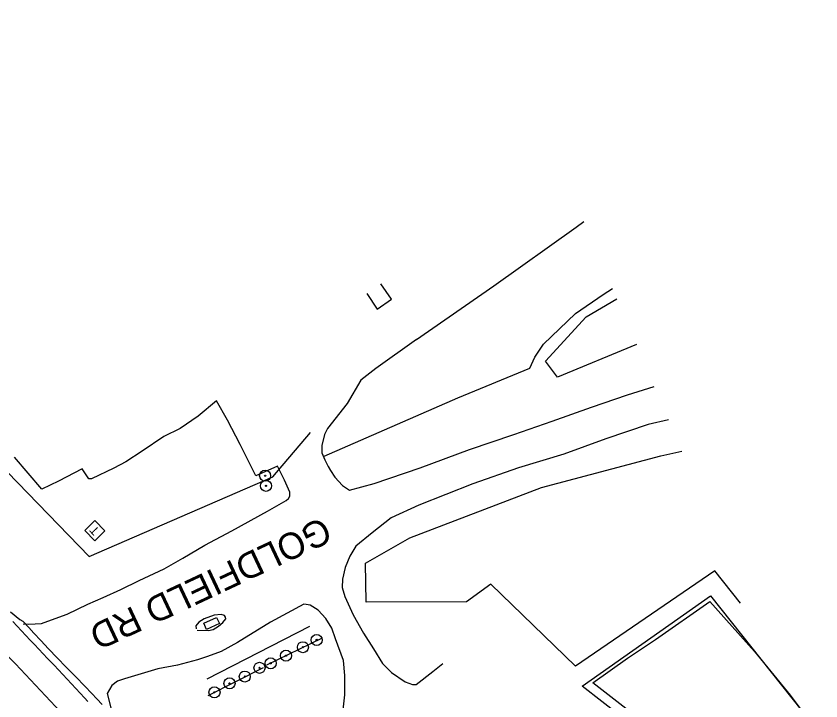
# Model space of a CAD drawing. Extents: x 474972 to 479313, y 498315 to 502691.
# Drawn here: x 477234.5 to 477551.7, y 500171.9 to 500442.1 of the extents above; entities that cross this region are included whole.
import ezdxf

# ---------------------------------------------------------------- set-up
doc = ezdxf.new("R2010")
doc.units = 0
for name, color, linetype in [('Exist Horizontal Alignment', 7, 'Continuous'), ('Exist Other Culture Area Outline', 7, 'Continuous'), ('Exist Other Culture Fence Line', 7, 'Continuous'), ('Exist Other Culture Gate', 7, 'Continuous'), ('Exist Other Culture Sign', 7, 'Continuous'), ('Exist Other Culture Sign Post CELL', 7, 'Continuous'), ('Exist Roads EOP', 7, 'Continuous'), ('Exist Roads EOT', 7, 'Continuous'), ('Exist Roads Soil', 7, 'Continuous'), ('Exist Roads Soil Text', 7, 'Continuous'), ('Exist Utilities Other Located Object CELL', 7, 'Continuous'), ('Exist Utilities Telephone Pedestal CELL', 7, 'Continuous'), ('Exist Vegetation Woods Line', 7, 'Continuous')]:
    doc.layers.add(name, color=color, linetype=linetype)

msp = doc.modelspace()

# ---------------------------------------------------------------- linework, layer by layer
at = {"layer": 'Exist Horizontal Alignment'}
msp.add_arc((475159.06, 498211.82), 2864.54, 37.33366, 48.4381, dxfattribs=at)
at = {"layer": 'Exist Other Culture Area Outline'}
msp.add_lwpolyline([(477372.66, 500332.68), (477376.85, 500326.48), (477382.44, 500330.4), (477378.3, 500336.51)], dxfattribs=at)
msp.add_lwpolyline([(477314.6, 500202.42), (477309.52, 500200.17), (477308.43, 500202.63), (477313.51, 500204.88)], close=True, dxfattribs=at)
at = {"layer": 'Exist Other Culture Fence Line'}
msp.add_line((477309.84, 500180.65), (477350.19, 500201.45), dxfattribs=at)
for points in [[(477039.4, 500442.07), (477096.14, 500405.12), (477127.29, 500368.44), (477206.77, 500287.2), (477263.29, 500228.94), (477335.66, 500260.31)], [(477355.92, 500268.54), (477408.61, 500291.48), (477437.03, 500303.18), (477439, 500307.6), (477442.35, 500312.6), (477454.97, 500324.77), (477465.82, 500332.23), (477469.57, 500334.57)], [(477493.59, 500150.54), (477480.89, 500159.66), (477457.6, 500177.83), (477508.16, 500213.44), (477544.32, 500167.89)]]:
    msp.add_lwpolyline(points, dxfattribs=at)
at = {"layer": 'Exist Other Culture Gate'}
msp.add_line((477335.66, 500260.31), (477350.53, 500277.77), dxfattribs=at)
at = {"layer": 'Exist Other Culture Sign'}
for p, q in [((477354.81, 500196.63), (477333.11, 500186.02)), ((477331.82, 500185.01), (477310.05, 500173.91))]:
    msp.add_line(p, q, dxfattribs=at)
at = {"layer": 'Exist Other Culture Sign Post CELL'}
for centre, radius in [((477352.97, 500196.01), 2.18), ((477352.97, 500196.01), 0.24), ((477347.52, 500193.13), 2.18), ((477347.52, 500193.13), 0.24), ((477340.86, 500189.8), 2.18), ((477340.86, 500189.8), 0.24), ((477330.42, 500185), 2.18), ((477334.82, 500186.8), 2.18), ((477334.82, 500186.8), 0.24), ((477324.61, 500181.56), 2.18), ((477330.42, 500185), 0.24), ((477318.6, 500178.86), 2.18), ((477324.61, 500181.56), 0.24), ((477312.67, 500175.35), 2.18), ((477318.6, 500178.86), 0.24), ((477312.67, 500175.35), 0.24)]:
    msp.add_circle(centre, radius, dxfattribs=at)
at = {"layer": 'Exist Roads EOP'}
msp.add_lwpolyline([(477232.26, 500207.11), (477235.93, 500204.1), (477237.07, 500203.39), (477237.37, 500203.15), (477239.54, 500200.85), (477241.51, 500198.72), (477244.16, 500195.84), (477247.28, 500192.5), (477250.62, 500188.97), (477254.18, 500185.27), (477257.98, 500181.39), (477261.51, 500177.78), (477264.3, 500174.92), (477266.33, 500172.8), (477268.45, 500170.49)], dxfattribs=at)
at = {"layer": 'Exist Roads EOT'}
msp.add_lwpolyline([(477262.8, 500171.72), (477261.4, 500173.22), (477259.69, 500175.05), (477257.98, 500176.87), (477256.27, 500178.7), (477254.57, 500180.52), (477252.86, 500182.35), (477251.15, 500184.17), (477249.44, 500186), (477247.73, 500187.82), (477246.9, 500188.71), (477245.18, 500190.52), (477243.46, 500192.33), (477241.74, 500194.15), (477240.02, 500195.96), (477238.3, 500197.77), (477236.58, 500199.58), (477234.85, 500201.4), (477233.13, 500203.21)], dxfattribs=at)
at = {"layer": 'Exist Roads Soil'}
for points in [[(477392.33, 500314.47), (477422.76, 500335.64), (477455.2, 500358.85), (477458.29, 500361.04)], [(477392.33, 500314.47), (477376.22, 500303.07), (477370.39, 500298.52), (477365.01, 500289.3), (477357.25, 500279.45), (477355.99, 500277), (477354.97, 500272.66), (477354.99, 500269.85), (477356.11, 500267), (477357.44, 500264.38), (477358.46, 500262.85), (477360.14, 500260.21), (477363.07, 500256.93), (477365.91, 500255.07), (477375.57, 500257.65), (477393.7, 500263.94), (477413.17, 500271.11), (477430.63, 500277.04), (477445.72, 500282.31), (477461.22, 500287.76), (477475.48, 500292.63), (477486.04, 500295.92)], [(477237.26, 500202.37), (477239.45, 500202.23), (477244.46, 500202.54), (477248.38, 500203.89), (477254.58, 500206.21), (477262.69, 500210.17), (477268.73, 500212.71), (477275.74, 500215.91), (477282.93, 500219.46), (477292.82, 500224.03), (477300.24, 500228.23), (477308.92, 500233.32), (477319.51, 500239.07), (477333.51, 500246.79), (477340.94, 500251.03), (477341.79, 500251.81), (477342.32, 500252.71), (477342.4, 500254.25), (477340.29, 500258.98), (477338.45, 500262.75), (477337.45, 500264.53), (477328.91, 500260.76), (477322.81, 500273.04), (477317.8, 500282.67), (477313.44, 500290.3), (477306.26, 500284.21), (477299.14, 500279.4), (477292.74, 500276.26), (477284.18, 500270.51), (477277.7, 500266.19), (477273.03, 500263.78), (477264.25, 500259.56), (477263.1, 500259.52), (477260.46, 500263.53), (477251.14, 500258.64), (477244.67, 500255.5), (477233.83, 500268.08)], [(477491.62, 500282.83), (477483.6, 500281.01), (477466.88, 500275.35), (477450.31, 500269.33), (477432.54, 500263.87), (477414.44, 500257.52), (477393.25, 500249.18)], [(477393.25, 500249.18), (477382.33, 500244.17), (477374.87, 500238.3), (477368.4, 500233.04), (477366, 500228.99), (477364.13, 500224.62), (477363.07, 500219.99), (477362.97, 500216.69), (477364.01, 500213.11), (477367.28, 500205.92), (477371.4, 500198.7), (477375.35, 500192.44), (477378.9, 500186.74), (477382.42, 500183.15), (477387.89, 500179.49), (477390.73, 500178.37), (477392.18, 500178.44), (477398.78, 500183.53), (477402.64, 500186.65)], [(477363.13, 500166.11), (477364.03, 500174.34), (477363.99, 500181.97), (477363.47, 500187.9), (477360.34, 500196.37), (477358.91, 500200.66), (477356.54, 500204.44), (477353.53, 500207.68), (477350.42, 500209.71), (477348.87, 500210), (477347.88, 500210.09), (477334.79, 500203.05), (477321.68, 500195.04), (477315.3, 500191.46), (477309.88, 500189.46), (477306.03, 500188.12), (477298.06, 500186.04), (477290.33, 500184.62), (477277.22, 500180.71), (477274.51, 500179.7), (477272.22, 500178.06), (477270.34, 500174.9), (477273.29, 500163.54)], [(477478.37, 500166.21), (477461.76, 500179.1), (477475.49, 500188.87), (477486.48, 500196.2), (477507.98, 500211.11), (477525.55, 500191.41), (477539.61, 500174.25), (477551.7, 500158.05)], [(477305.89, 500199.84), (477310.31, 500199.74), (477312.11, 500200.18), (477314.2, 500201.39), (477315.91, 500202.91), (477317.2, 500204.3), (477317.08, 500204.98), (477316.58, 500205.67), (477315.3, 500205.98), (477312.61, 500205.78), (477308.62, 500204.34), (477306.5, 500203.06), (477305.27, 500201.54), (477305.41, 500200.36)]]:
    msp.add_lwpolyline(points, dxfattribs=at)
at = {"layer": 'Exist Utilities Other Located Object CELL'}
for centre, radius in [((477332.63, 500260.78), 2.18), ((477332.63, 500260.78), 0.24), ((477332.98, 500256.78), 2.18), ((477332.98, 500256.78), 0.24)]:
    msp.add_circle(centre, radius, dxfattribs=at)
at = {"layer": 'Exist Utilities Telephone Pedestal CELL'}
msp.add_line((477265.56, 500239.02), (477265.56, 500239.02), dxfattribs=at)
msp.add_lwpolyline([(477269.49, 500239.05), (477265.57, 500243.05), (477261.58, 500239.14), (477265.49, 500235.14), (477269.49, 500239.05)], dxfattribs=at)
at = {"layer": 'Exist Vegetation Woods Line'}
for points in [[(477478.98, 500312.48), (477447.92, 500299.71), (477443.16, 500306.02), (477459.18, 500323.49), (477471.26, 500330.6)], [(477519.95, 500210.51), (477509.85, 500223.27), (477454.93, 500185.62), (477421.58, 500218.05), (477411.98, 500211.04), (477372.48, 500210.92), (477372.19, 500226.24), (477389.69, 500236.29), (477441.63, 500256.1), (477488.64, 500268.6), (477496.88, 500270.49)]]:
    msp.add_lwpolyline(points, dxfattribs=at)

# ---------------------------------------------------------------- texts
at = {"layer": 'Exist Roads Soil Text'}
msp.add_text('GOLDFIELD RD', height=10.4, rotation=205.1826, dxfattribs=at).set_placement((477355.46, 500244.77))
at = {"layer": 'Exist Utilities Telephone Pedestal CELL'}
msp.add_text('T', height=3.42, rotation=134.3938, dxfattribs=at).set_placement((477267.58, 500239.41))

doc.saveas('drawing.dxf')
